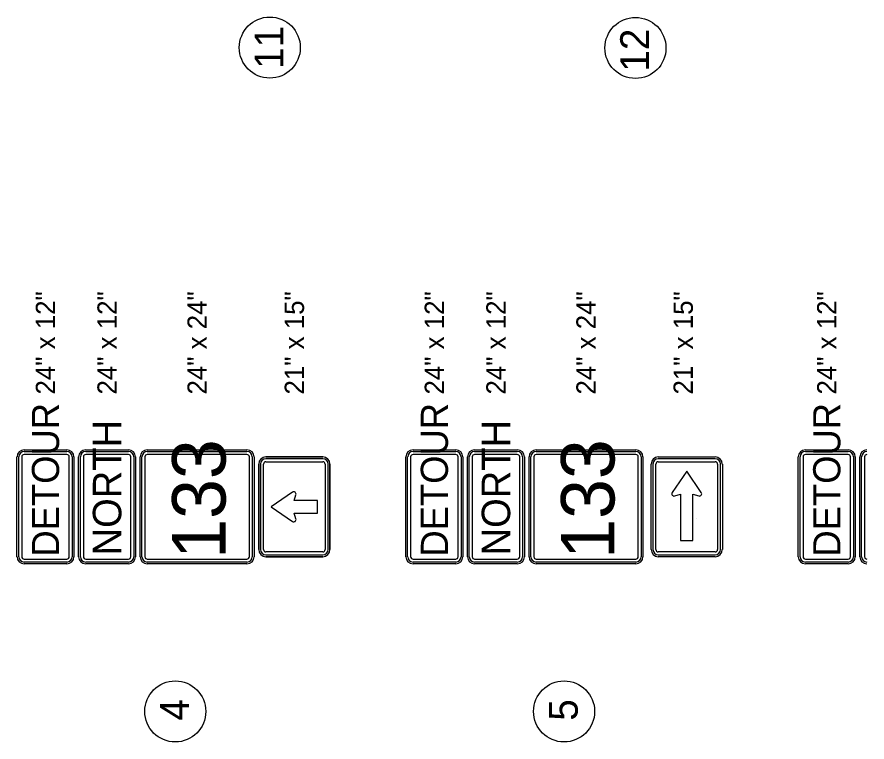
# Model space of a CAD drawing. Extents: x 1123038 to 1172987, y 554419 to 623636.
# Drawn here: x 1155864 to 1160788, y 559414 to 563611 of the extents above; entities that cross this region are included whole.
import ezdxf

# ---------------------------------------------------------------- set-up
doc = ezdxf.new("R2010")
doc.units = 0
doc.layers.add('D_Text_Standard', color=7, linetype='Continuous')
doc.layers.add('SIGNS TRAFFIC', color=7, linetype='Continuous')

msp = doc.modelspace()

# ---------------------------------------------------------------- linework, layer by layer
at = {"layer": 'D_Text_Standard'}
for centre in [(1157328.3, 563434.1), (1159446.6, 563432), (1156780.4, 559590.8), (1159033.3, 559590.8)]:
    msp.add_circle(centre, 176.8, dxfattribs=at)
at = {"layer": 'SIGNS TRAFFIC'}
for p, q in [((1157274.4, 561023), (1157274.4, 560528)), ((1159547.8, 561023), (1159547.8, 560528)), ((1157468.7, 560811.6), (1157479.6, 560845.4)), ((1159673.9, 560838.5), (1159707.6, 560849.3)), ((1159707.6, 560849.3), (1159707.7, 560579.6)), ((1159779.8, 560579.6), (1159779.8, 560849.3)), ((1159779.8, 560849.3), (1159813.6, 560838.5)), ((1157604.4, 560811.6), (1157468.7, 560811.6)), ((1157604.4, 560739.4), (1157604.4, 560811.6)), ((1157479.6, 560705.7), (1157468.7, 560739.4)), ((1157468.7, 560739.4), (1157604.4, 560739.4)), ((1159707.6, 560579.6), (1159779.8, 560579.6))]:
    msp.add_line(p, q, dxfattribs=at)
for points in [[(1155905, 561105.5), (1156152.5, 561105.5)], [(1155905, 561105.5), (1156152.5, 561105.5)], [(1155905, 561095.2), (1156152.5, 561095.2)], [(1156152.5, 561078), (1155905, 561078)], [(1156261.8, 561105.5), (1156509.3, 561105.5)], [(1156261.8, 561105.5), (1156509.3, 561105.5)], [(1156261.8, 561095.2), (1156509.3, 561095.2)], [(1156509.3, 561078), (1156261.8, 561078)], [(1156618.6, 561105.5), (1157196.1, 561105.5)], [(1156618.6, 561105.5), (1157196.1, 561105.5)], [(1156618.6, 561095.2), (1157196.1, 561095.2)], [(1157196.1, 561078), (1156618.6, 561078)], [(1158157.9, 561105.5), (1158405.4, 561105.5)], [(1158157.9, 561105.5), (1158405.4, 561105.5)], [(1158157.9, 561095.2), (1158405.4, 561095.2)], [(1158405.4, 561078), (1158157.9, 561078)], [(1158514.7, 561105.5), (1158762.2, 561105.5)], [(1158514.7, 561105.5), (1158762.2, 561105.5)], [(1158514.7, 561095.2), (1158762.2, 561095.2)], [(1158762.2, 561078), (1158514.7, 561078)], [(1158871.5, 561105.5), (1159449, 561105.5)], [(1158871.5, 561105.5), (1159449, 561105.5)], [(1158871.5, 561095.2), (1159449, 561095.2)], [(1159449, 561078), (1158871.5, 561078)], [(1160431.2, 561105.5), (1160678.7, 561105.5)], [(1160431.2, 561105.5), (1160678.7, 561105.5)], [(1160431.2, 561095.2), (1160678.7, 561095.2)], [(1160678.7, 561078), (1160431.2, 561078)], [(1155863.7, 560486.8), (1155863.7, 561064.3)], [(1155863.7, 560486.8), (1155863.7, 561064.3)], [(1155874, 560486.8), (1155874, 561064.3)], [(1155891.2, 561064.3), (1155891.2, 560486.8)], [(1156166.2, 560486.8), (1156166.2, 561064.3)], [(1156183.4, 561064.3), (1156183.4, 560486.8)], [(1156193.7, 561064.3), (1156193.7, 560486.8)], [(1156193.7, 561064.3), (1156193.7, 560486.8)], [(1156220.5, 560486.8), (1156220.5, 561064.3)], [(1156220.5, 560486.8), (1156220.5, 561064.3)], [(1156230.8, 560486.8), (1156230.8, 561064.3)], [(1156248, 561064.3), (1156248, 560486.8)], [(1156523, 560486.8), (1156523, 561064.3)], [(1156540.2, 561064.3), (1156540.2, 560486.8)], [(1156550.5, 561064.3), (1156550.5, 560486.8)], [(1156550.5, 561064.3), (1156550.5, 560486.8)], [(1156577.3, 560486.8), (1156577.3, 561064.3)], [(1156577.3, 560486.8), (1156577.3, 561064.3)], [(1156587.6, 560486.8), (1156587.6, 561064.3)], [(1156604.8, 561064.3), (1156604.8, 560486.8)], [(1157209.8, 560486.8), (1157209.8, 561064.3)], [(1157227, 561064.3), (1157227, 560486.8)], [(1157237.3, 561064.3), (1157237.3, 560486.8)], [(1157237.3, 561064.3), (1157237.3, 560486.8)], [(1157305.4, 561064.3), (1157635.4, 561064.3)], [(1157635.4, 561064.3), (1157305.4, 561064.3)], [(1157635.4, 561053.9), (1157305.4, 561053.9)], [(1157305.4, 561036.7), (1157635.4, 561036.7)], [(1158116.6, 560486.8), (1158116.6, 561064.3)], [(1158116.6, 560486.8), (1158116.6, 561064.3)], [(1158126.9, 560486.8), (1158126.9, 561064.3)], [(1158144.1, 561064.3), (1158144.1, 560486.8)], [(1158419.1, 560486.8), (1158419.1, 561064.3)], [(1158436.3, 561064.3), (1158436.3, 560486.8)], [(1158446.6, 561064.3), (1158446.6, 560486.8)], [(1158446.6, 561064.3), (1158446.6, 560486.8)], [(1158473.4, 560486.8), (1158473.4, 561064.3)], [(1158473.4, 560486.8), (1158473.4, 561064.3)], [(1158483.7, 560486.8), (1158483.7, 561064.3)], [(1158500.9, 561064.3), (1158500.9, 560486.8)], [(1158775.9, 560486.8), (1158775.9, 561064.3)], [(1158793.1, 561064.3), (1158793.1, 560486.8)], [(1158803.4, 561064.3), (1158803.4, 560486.8)], [(1158803.4, 561064.3), (1158803.4, 560486.8)], [(1158830.2, 560486.8), (1158830.2, 561064.3)], [(1158830.2, 560486.8), (1158830.2, 561064.3)], [(1158840.5, 560486.8), (1158840.5, 561064.3)], [(1158857.7, 561064.3), (1158857.7, 560486.8)], [(1159462.7, 560486.8), (1159462.7, 561064.3)], [(1159479.9, 561064.3), (1159479.9, 560486.8)], [(1159490.2, 561064.3), (1159490.2, 560486.8)], [(1159490.2, 561064.3), (1159490.2, 560486.8)], [(1159578.7, 561064.3), (1159908.7, 561064.3)], [(1159908.7, 561053.9), (1159578.7, 561053.9)], [(1159578.7, 561036.7), (1159908.7, 561036.7)], [(1160390, 560486.8), (1160390, 561064.3)], [(1160390, 560486.8), (1160390, 561064.3)], [(1160400.3, 560486.8), (1160400.3, 561064.3)], [(1160417.5, 561064.3), (1160417.5, 560486.8)], [(1160692.4, 560486.8), (1160692.4, 561064.3)], [(1160709.6, 561064.3), (1160709.6, 560486.8)], [(1160720, 561064.3), (1160720, 560486.8)], [(1160720, 561064.3), (1160720, 560486.8)], [(1160746.8, 560486.8), (1160746.8, 561064.3)], [(1160746.8, 560486.8), (1160746.8, 561064.3)], [(1160757.1, 560486.8), (1160757.1, 561064.3)], [(1160774.3, 561064.3), (1160774.3, 560486.8)], [(1157264.1, 560528), (1157264.1, 561023)], [(1157264.1, 561023), (1157264.1, 560528)], [(1157291.6, 560528), (1157291.6, 561023)], [(1157649.1, 561023), (1157649.1, 560528)], [(1157666.3, 560528), (1157666.3, 561023)], [(1157676.6, 561023), (1157676.6, 560528)], [(1157676.6, 560528), (1157676.6, 561023)], [(1159537.5, 560528), (1159537.5, 561023)], [(1159565, 560528), (1159565, 561023)], [(1159828.2, 560858), (1159743.7, 560981.8), (1159659.2, 560858)], [(1159922.4, 561023), (1159922.4, 560528)], [(1159939.6, 560528), (1159939.6, 561023)], [(1159950, 561023), (1159950, 560528)], [(1157460, 560860), (1157336.3, 560775.5), (1157460, 560691)], [(1159801.5, 560705.4), (1159801.5, 560705.5)], [(1157635.4, 560514.3), (1157305.4, 560514.3)], [(1157305.4, 560497.1), (1157635.4, 560497.1)], [(1157635.4, 560486.8), (1157305.4, 560486.8)], [(1157305.4, 560486.8), (1157635.4, 560486.8)], [(1159908.7, 560514.3), (1159578.7, 560514.3)], [(1159578.7, 560497.1), (1159908.7, 560497.1)], [(1159908.7, 560486.8), (1159578.7, 560486.8)], [(1155905, 560473), (1156152.5, 560473)], [(1156152.5, 560455.8), (1155905, 560455.8)], [(1156152.5, 560445.5), (1155905, 560445.5)], [(1156152.5, 560445.5), (1155905, 560445.5)], [(1156261.8, 560473), (1156509.3, 560473)], [(1156509.3, 560455.8), (1156261.8, 560455.8)], [(1156509.3, 560445.5), (1156261.8, 560445.5)], [(1156509.3, 560445.5), (1156261.8, 560445.5)], [(1156618.6, 560473), (1157196.1, 560473)], [(1157196.1, 560455.8), (1156618.6, 560455.8)], [(1157196.1, 560445.5), (1156618.6, 560445.5)], [(1157196.1, 560445.5), (1156618.6, 560445.5)], [(1158157.9, 560473), (1158405.4, 560473)], [(1158405.4, 560455.8), (1158157.9, 560455.8)], [(1158405.4, 560445.5), (1158157.9, 560445.5)], [(1158405.4, 560445.5), (1158157.9, 560445.5)], [(1158514.7, 560473), (1158762.2, 560473)], [(1158762.2, 560455.8), (1158514.7, 560455.8)], [(1158762.2, 560445.5), (1158514.7, 560445.5)], [(1158762.2, 560445.5), (1158514.7, 560445.5)], [(1158871.5, 560473), (1159449, 560473)], [(1159449, 560455.8), (1158871.5, 560455.8)], [(1159449, 560445.5), (1158871.5, 560445.5)], [(1159449, 560445.5), (1158871.5, 560445.5)], [(1160431.2, 560473), (1160678.7, 560473)], [(1160678.7, 560455.8), (1160431.2, 560455.8)], [(1160678.7, 560445.5), (1160431.2, 560445.5)], [(1160678.7, 560445.5), (1160431.2, 560445.5)]]:
    msp.add_lwpolyline(points, dxfattribs=at)
for centre, radius, start, end in [((1155905, 561064.3), 41.2, 90, 180), ((1155905, 561064.3), 41.2, 90, 180), ((1155905, 561064.3), 30.9, 90, 180), ((1155905, 561064.3), 13.7, 90, 180), ((1156152.5, 561064.3), 41.2, 360, 90), ((1156152.5, 561064.3), 41.2, 360, 90), ((1156152.5, 561064.3), 30.9, 360, 90), ((1156152.5, 561064.3), 13.7, 360, 90), ((1156261.8, 561064.3), 41.2, 90, 180), ((1156261.8, 561064.3), 41.2, 90, 180), ((1156261.8, 561064.3), 30.9, 90, 180), ((1156261.8, 561064.3), 13.7, 90, 180), ((1156509.3, 561064.3), 41.2, 360, 90), ((1156509.3, 561064.3), 41.2, 360, 90), ((1156509.3, 561064.3), 30.9, 360, 90), ((1156509.3, 561064.3), 13.7, 360, 90), ((1156618.6, 561064.3), 41.2, 90, 180), ((1156618.6, 561064.3), 41.2, 90, 180), ((1156618.6, 561064.3), 30.9, 90, 180), ((1156618.6, 561064.3), 13.7, 90, 180), ((1157196.1, 561064.3), 41.2, 360, 90), ((1157196.1, 561064.3), 41.2, 360, 90), ((1157196.1, 561064.3), 30.9, 360, 90), ((1157196.1, 561064.3), 13.7, 360, 90), ((1158157.9, 561064.3), 41.2, 90, 180), ((1158157.9, 561064.3), 41.2, 90, 180), ((1158157.9, 561064.3), 30.9, 90, 180), ((1158157.9, 561064.3), 13.7, 90, 180), ((1158405.4, 561064.3), 41.2, 360, 90), ((1158405.4, 561064.3), 41.2, 360, 90), ((1158405.4, 561064.3), 30.9, 360, 90), ((1158405.4, 561064.3), 13.7, 360, 90), ((1158514.7, 561064.3), 41.2, 90, 180), ((1158514.7, 561064.3), 41.2, 90, 180), ((1158514.7, 561064.3), 30.9, 90, 180), ((1158514.7, 561064.3), 13.7, 90, 180), ((1158762.2, 561064.3), 41.2, 360, 90), ((1158762.2, 561064.3), 41.2, 360, 90), ((1158762.2, 561064.3), 30.9, 360, 90), ((1158762.2, 561064.3), 13.7, 360, 90), ((1158871.5, 561064.3), 41.2, 90, 180), ((1158871.5, 561064.3), 41.2, 90, 180), ((1158871.5, 561064.3), 30.9, 90, 180), ((1158871.5, 561064.3), 13.7, 90, 180), ((1159449, 561064.3), 41.2, 360, 90), ((1159449, 561064.3), 41.2, 360, 90), ((1159449, 561064.3), 30.9, 360, 90), ((1159449, 561064.3), 13.7, 360, 90), ((1160431.2, 561064.3), 41.2, 90, 180), ((1160431.2, 561064.3), 41.2, 90, 180), ((1160431.2, 561064.3), 30.9, 90, 180), ((1160431.2, 561064.3), 13.7, 90, 180), ((1160678.7, 561064.3), 41.2, 360, 90), ((1160678.7, 561064.3), 41.2, 360, 90), ((1160678.7, 561064.3), 30.9, 360, 90), ((1160678.7, 561064.3), 13.7, 360, 90), ((1160788, 561064.3), 41.2, 90, 180), ((1160788, 561064.3), 41.2, 90, 180), ((1160788, 561064.3), 30.9, 90, 180), ((1160788, 561064.3), 13.7, 90, 180), ((1157305.4, 561023), 41.2, 90, 180), ((1157305.4, 561023), 41.2, 90, 180), ((1157305.4, 561023), 30.9, 90, 180), ((1157305.4, 561023), 13.7, 90, 180), ((1157635.4, 561023), 41.2, 360, 90), ((1157635.4, 561023), 41.2, 360, 90), ((1157635.4, 561023), 30.9, 360, 90), ((1157635.4, 561023), 13.7, 360, 90), ((1159578.7, 561023), 41.2, 90, 180), ((1159578.7, 561023), 30.9, 90, 180), ((1159578.7, 561023), 13.7, 90, 180), ((1159908.7, 561023), 41.2, 360, 90), ((1159908.7, 561023), 30.9, 360, 90), ((1159908.7, 561023), 13.7, 360, 90), ((1157467.3, 560849.3), 12.9, 342.1872, 124.3237), ((1159669.9, 560850.8), 12.9, 145.6763, 287.8128), ((1159817.5, 560850.8), 12.9, 252.1872, 34.3237), ((1157467.3, 560701.7), 12.9, 235.6763, 17.8128), ((1155905, 560486.8), 41.2, 180, 270), ((1155905, 560486.8), 41.2, 180, 270), ((1155905, 560486.8), 30.9, 180, 270), ((1155905, 560486.8), 13.7, 180, 270), ((1156152.5, 560486.8), 41.2, 270, 360), ((1156152.5, 560486.8), 41.2, 270, 360), ((1156152.5, 560486.8), 30.9, 270, 360), ((1156152.5, 560486.8), 13.7, 270, 360), ((1156261.8, 560486.8), 41.2, 180, 270), ((1156261.8, 560486.8), 41.2, 180, 270), ((1156261.8, 560486.8), 30.9, 180, 270), ((1156261.8, 560486.8), 13.7, 180, 270), ((1156509.3, 560486.8), 41.2, 270, 360), ((1156509.3, 560486.8), 41.2, 270, 360), ((1156509.3, 560486.8), 30.9, 270, 360), ((1156509.3, 560486.8), 13.7, 270, 360), ((1156618.6, 560486.8), 41.2, 180, 270), ((1156618.6, 560486.8), 41.2, 180, 270), ((1156618.6, 560486.8), 30.9, 180, 270), ((1156618.6, 560486.8), 13.7, 180, 270), ((1157196.1, 560486.8), 41.2, 270, 360), ((1157196.1, 560486.8), 41.2, 270, 360), ((1157196.1, 560486.8), 30.9, 270, 360), ((1157196.1, 560486.8), 13.7, 270, 360), ((1157305.4, 560528), 41.2, 180, 270), ((1157305.4, 560528), 41.2, 180, 270), ((1157305.4, 560528), 30.9, 180, 270), ((1157305.4, 560528), 13.7, 180, 270), ((1157635.4, 560528), 41.2, 270, 0), ((1157635.4, 560528), 41.2, 270, 0), ((1157635.4, 560528), 30.9, 270, 0), ((1157635.4, 560528), 13.7, 270, 0), ((1158157.9, 560486.8), 41.2, 180, 270), ((1158157.9, 560486.8), 41.2, 180, 270), ((1158157.9, 560486.8), 30.9, 180, 270), ((1158157.9, 560486.8), 13.7, 180, 270), ((1158405.4, 560486.8), 41.2, 270, 360), ((1158405.4, 560486.8), 41.2, 270, 360), ((1158405.4, 560486.8), 30.9, 270, 360), ((1158405.4, 560486.8), 13.7, 270, 360), ((1158514.7, 560486.8), 41.2, 180, 270), ((1158514.7, 560486.8), 41.2, 180, 270), ((1158514.7, 560486.8), 30.9, 180, 270), ((1158514.7, 560486.8), 13.7, 180, 270), ((1158762.2, 560486.8), 41.2, 270, 360), ((1158762.2, 560486.8), 41.2, 270, 360), ((1158762.2, 560486.8), 30.9, 270, 360), ((1158762.2, 560486.8), 13.7, 270, 360), ((1158871.5, 560486.8), 41.2, 180, 270), ((1158871.5, 560486.8), 41.2, 180, 270), ((1158871.5, 560486.8), 30.9, 180, 270), ((1158871.5, 560486.8), 13.7, 180, 270), ((1159449, 560486.8), 41.2, 270, 360), ((1159449, 560486.8), 41.2, 270, 360), ((1159449, 560486.8), 30.9, 270, 360), ((1159449, 560486.8), 13.7, 270, 360), ((1159578.7, 560528), 41.2, 180, 270), ((1159578.7, 560528), 30.9, 180, 270), ((1159578.7, 560528), 13.7, 180, 270), ((1159908.7, 560528), 41.2, 270, 0), ((1159908.7, 560528), 30.9, 270, 0), ((1159908.7, 560528), 13.7, 270, 0), ((1160431.2, 560486.8), 41.2, 180, 270), ((1160431.2, 560486.8), 41.2, 180, 270), ((1160431.2, 560486.8), 30.9, 180, 270), ((1160431.2, 560486.8), 13.7, 180, 270), ((1160678.7, 560486.8), 41.2, 270, 360), ((1160678.7, 560486.8), 41.2, 270, 360), ((1160678.7, 560486.8), 30.9, 270, 360), ((1160678.7, 560486.8), 13.7, 270, 360), ((1160788, 560486.8), 41.2, 180, 270), ((1160788, 560486.8), 41.2, 180, 270), ((1160788, 560486.8), 30.9, 180, 270), ((1160788, 560486.8), 13.7, 180, 270)]:
    msp.add_arc(centre, radius, start, end, dxfattribs=at)

# ---------------------------------------------------------------- texts
at = {"layer": 'D_Text_Standard'}
for s, height, p in [('11', 167.06, (1157407.1, 563311.1)), ('12', 167.06, (1159525.4, 563295.1)), ('24" x 12"', 111.99, (1156084.7, 561425.5)), ('24" x 12"', 111.99, (1156441.5, 561425.5)), ('24" x 24"', 111.99, (1156963.3, 561425.5)), ('21" x 15"', 111.99, (1157526.4, 561425.5)), ('24" x 12"', 111.99, (1158337.6, 561425.5)), ('24" x 12"', 111.99, (1158694.4, 561425.5)), ('24" x 24"', 111.99, (1159216.2, 561425.5)), ('21" x 15"', 111.99, (1159779.3, 561425.5)), ('24" x 12"', 111.99, (1160611, 561425.5)), ('4', 167.1, (1156859.2, 559537.4)), ('5', 167.1, (1159112.1, 559537.2))]:
    msp.add_text(s, height=height, rotation=90, dxfattribs=at).set_placement(p)
at = {"layer": 'SIGNS TRAFFIC'}
for s, height, p in [('DETOUR', 157.5, (1156107.5, 560487.4)), ('DETOUR', 157.5, (1158360.4, 560487.4)), ('DETOUR', 157.5, (1160633.7, 560487.4)), ('NORTH', 165, (1156468, 560493.9)), ('NORTH', 165, (1158720.9, 560493.9)), ('133', 310, (1157072.3, 560474.9)), ('133', 310, (1159325.2, 560474.9))]:
    msp.add_text(s, height=height, rotation=90, dxfattribs=at).set_placement(p)

doc.saveas('drawing.dxf')
